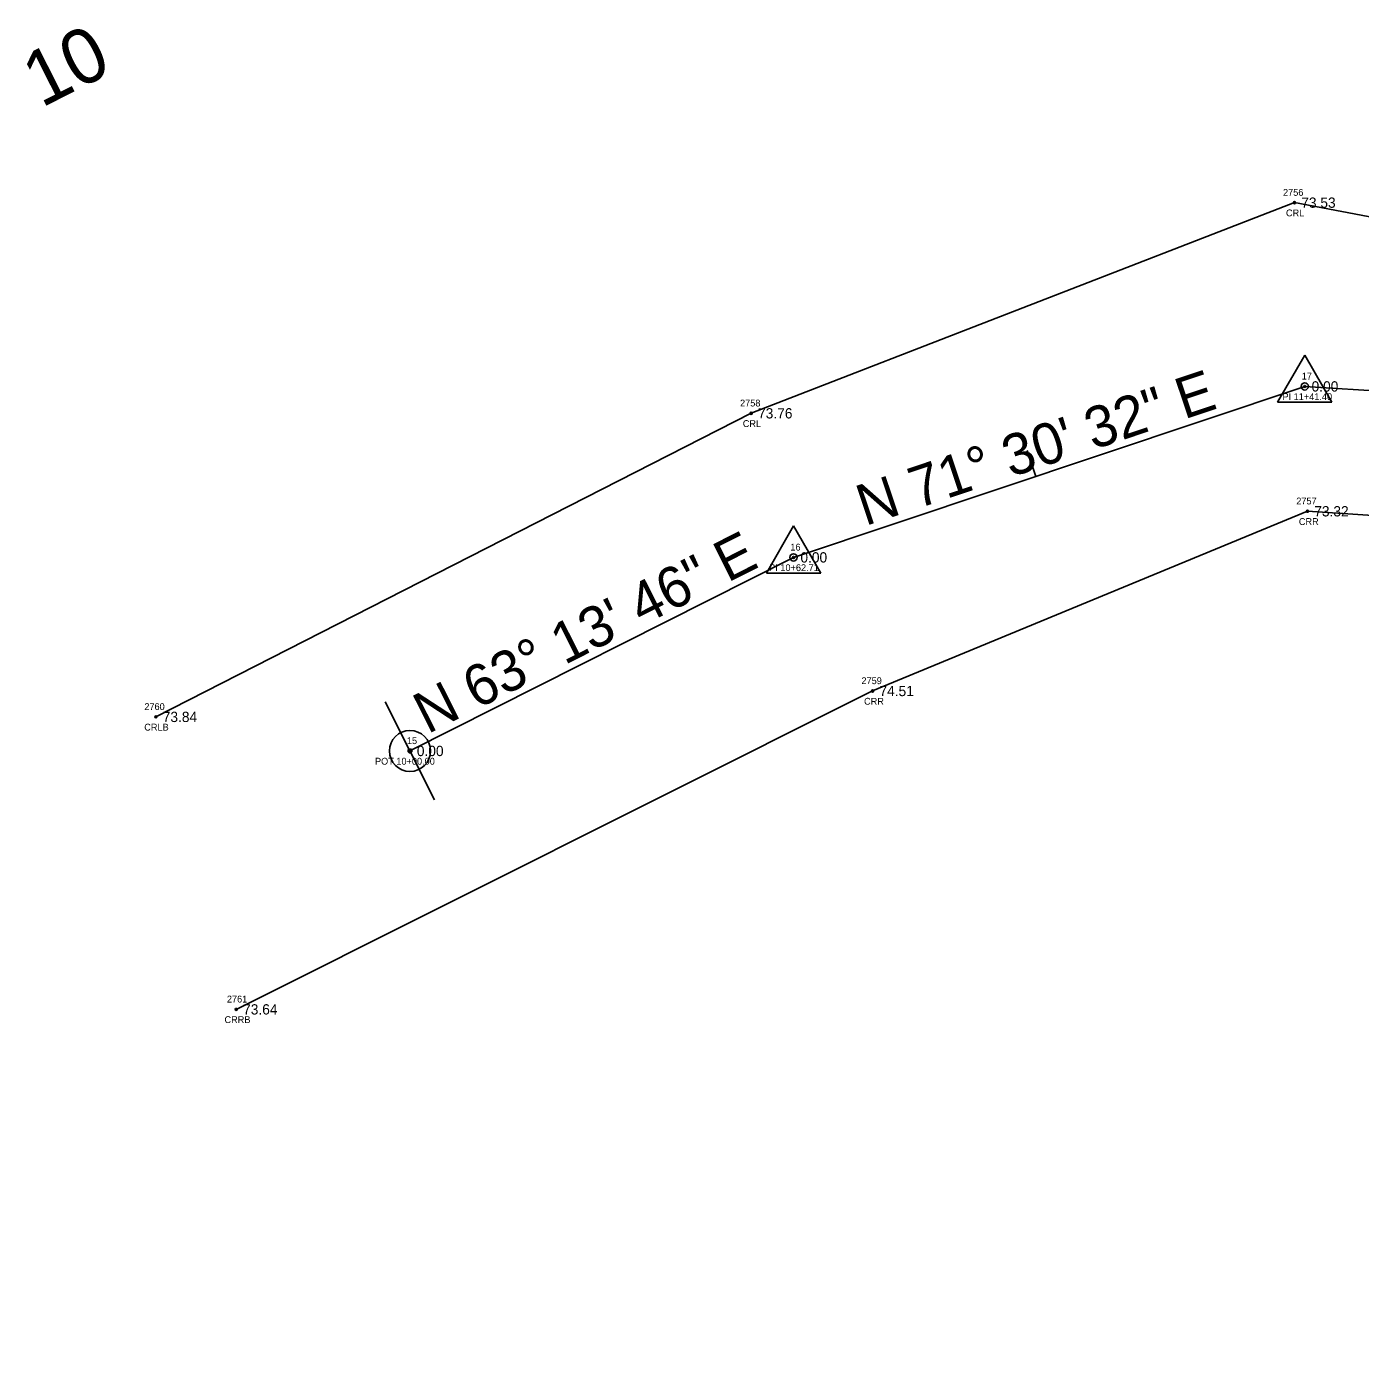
# Model space of a CAD drawing. Extents: x 2139392 to 2143384, y 505395 to 510520.
# Drawn here: x 2140207.5 to 2140402.1, y 508334.6 to 508531 of the extents above; entities that cross this region are included whole.
import ezdxf

# ---------------------------------------------------------------- set-up
doc = ezdxf.new("R2010")
doc.units = 0
for name, color, linetype in [('RD_EX_H2O', 7, 'Continuous'), ('RD_EX_H2O_txCode', 7, 'Continuous'), ('RD_EX_TX_H2O_ELEV', 7, 'Continuous'), ('RD_HC_Cl', 7, 'Continuous'), ('RD_HC_Data', 7, 'Continuous'), ('RD_HC_Data_Tic', 7, 'Continuous'), ('RD_HC_Survey_ELEV', 7, 'Continuous'), ('RD_HC_TX_Sta50', 7, 'Continuous'), ('RD_HC_txCode', 7, 'Continuous'), ('RD_SMD_Locator', 7, 'Continuous')]:
    doc.layers.add(name, color=color, linetype=linetype)

msp = doc.modelspace()

# ---------------------------------------------------------------- linework, layer by layer
at = {"layer": 'RD_EX_H2O'}
for points in [[(2140563.87, 508492.1), (2140548.73, 508480.68), (2140450.57, 508494.36), (2140392.48, 508505.39), (2140313.19, 508474.64), (2140226.29, 508430.33)], [(2140666.06, 508334.55), (2140601.63, 508399.26), (2140555.06, 508452.56), (2140445.76, 508456.93), (2140394.38, 508460.34), (2140330.91, 508434.11), (2140238.02, 508387.64)]]:
    msp.add_lwpolyline(points, dxfattribs=at)
at = {"layer": 'RD_HC_Cl'}
for p, q in [((2140319.37, 508453.61), (2140393.99, 508478.57)), ((2140393.99, 508478.57), (2140555.86, 508468.05)), ((2140263.38, 508425.36), (2140319.37, 508453.61))]:
    msp.add_line(p, q, dxfattribs=at)
at = {"layer": 'RD_HC_Data'}
for p, q in [((2140390.02, 508476.27), (2140394, 508483.15)), ((2140394, 508483.15), (2140397.96, 508476.27)), ((2140390.02, 508476.27), (2140397.96, 508476.27)), ((2140315.4, 508451.32), (2140319.37, 508458.2)), ((2140319.37, 508458.2), (2140323.34, 508451.32)), ((2140315.4, 508451.32), (2140323.34, 508451.32))]:
    msp.add_line(p, q, dxfattribs=at)
for centre, radius in [((2140393.99, 508478.57), 0.529), ((2140319.37, 508453.61), 0.529), ((2140263.38, 508425.36), 3), ((2140263.38, 508425.36), 0.282)]:
    msp.add_circle(centre, radius, dxfattribs=at)
at = {"layer": 'RD_HC_Data_Tic'}
for p, q in [((2140354.73, 508465.44), (2140353.46, 508469.23)), ((2140263.38, 508425.36), (2140259.78, 508432.51)), ((2140263.38, 508425.36), (2140266.98, 508418.22))]:
    msp.add_line(p, q, dxfattribs=at)
at = {"layer": 'RD_SMD_Locator'}
for centre in [(2140392.48, 508505.39), (2140393.99, 508478.57), (2140313.19, 508474.64), (2140394.38, 508460.34), (2140319.37, 508453.61), (2140330.91, 508434.11), (2140226.29, 508430.33), (2140263.38, 508425.36), (2140238.02, 508387.64)]:
    msp.add_circle(centre, 0.15, dxfattribs=at)

# ---------------------------------------------------------------- texts
at = {"layer": 'RD_EX_H2O_txCode'}
for s, p in [('2756', (2140390.82, 508506.39)), ('CRL', (2140391.25, 508503.39)), ('2758', (2140311.56, 508475.64)), ('CRL', (2140311.96, 508472.64)), ('2757', (2140392.75, 508461.34)), ('CRR', (2140393.13, 508458.34)), ('2759', (2140329.28, 508435.11)), ('CRR', (2140329.66, 508432.11)), ('2760', (2140224.6, 508431.33)), ('CRLB', (2140224.59, 508428.33)), ('2761', (2140236.65, 508388.64)), ('CRRB', (2140236.3, 508385.64))]:
    msp.add_text(s, height=1, dxfattribs=at).set_placement(p)
at = {"layer": 'RD_EX_TX_H2O_ELEV'}
for s, p in [('73.53', (2140393.48, 508504.64)), ('73.76', (2140314.19, 508473.89)), ('73.32', (2140395.38, 508459.59)), ('74.51', (2140331.91, 508433.36)), ('73.84', (2140227.29, 508429.58)), ('73.64', (2140239.02, 508386.89))]:
    msp.add_text(s, height=1.5, dxfattribs=at).set_placement(p)
at = {"layer": 'RD_HC_Data'}
for s, rotation, p in [('N 71%%d 30\' 32" E', 18.491, (2140329.83, 508458.16)), ('N 63%%d 13\' 46" E', 26.7707, (2140265.94, 508427.78))]:
    msp.add_text(s, height=6, rotation=rotation, dxfattribs=at).set_placement(p)
at = {"layer": 'RD_HC_Survey_ELEV'}
for p in [(2140394.99, 508477.82), (2140320.37, 508452.86), (2140264.38, 508424.61)]:
    msp.add_text('0.00', height=1.5, dxfattribs=at).set_placement(p)
at = {"layer": 'RD_HC_TX_Sta50'}
msp.add_text('10', height=8, rotation=26.7707, dxfattribs=at).set_placement((2140209.56, 508519.18))
at = {"layer": 'RD_HC_txCode'}
for s, p in [('17', (2140393.55, 508479.57)), ('PI 11+41.40', (2140390.74, 508476.57)), ('16', (2140318.9, 508454.61)), ('PI 10+62.71', (2140315.81, 508451.61)), ('15', (2140262.93, 508426.36)), ('POT 10+00.00', (2140258.27, 508423.36))]:
    msp.add_text(s, height=1, dxfattribs=at).set_placement(p)

doc.saveas('drawing.dxf')
